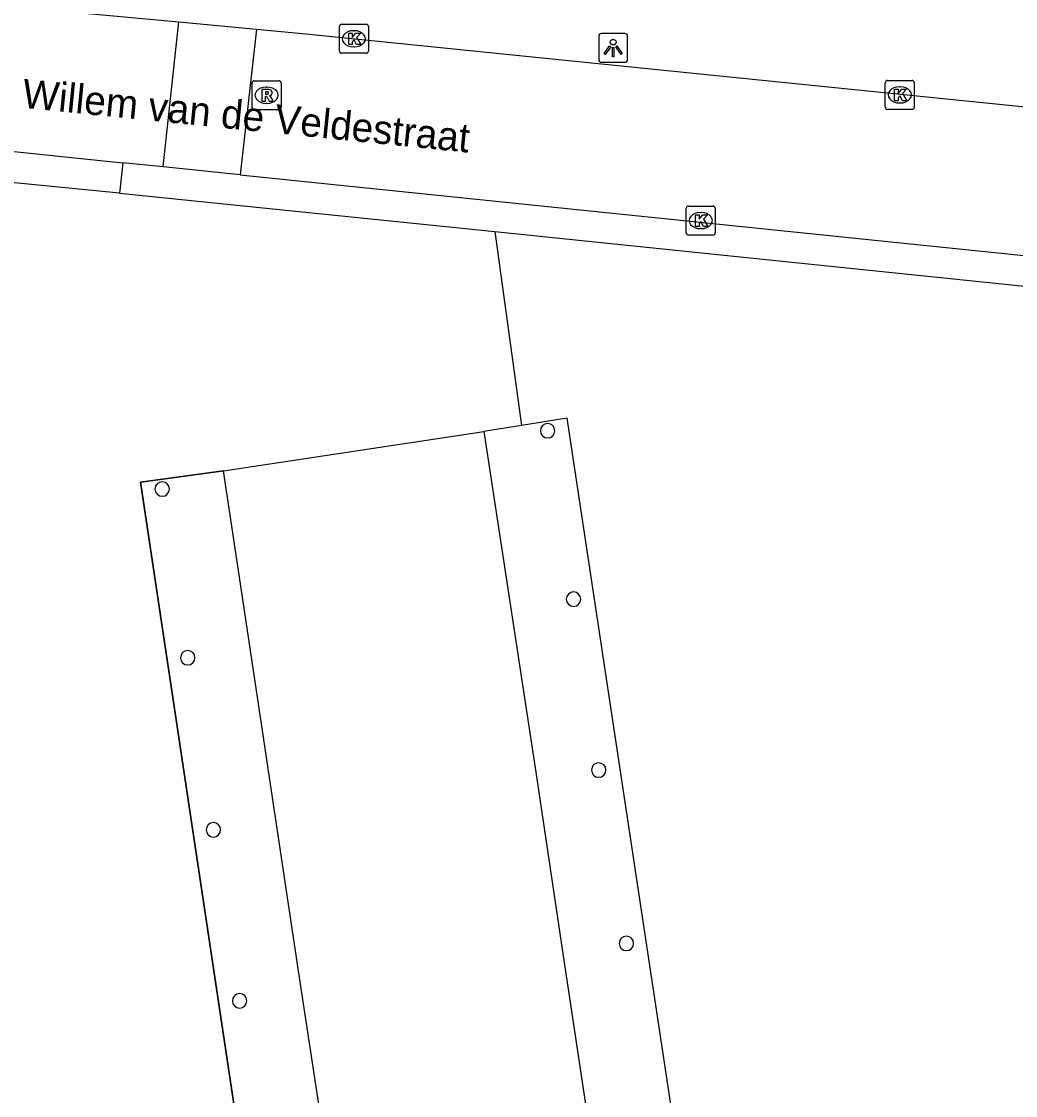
# Model space of a CAD drawing. Extents: x 163010 to 163853, y 382793 to 383982.
# Drawn here: x 163198.03 to 163232.4, y 383366.94 to 383404.07 of the extents above; entities that cross this region are included whole.
import ezdxf

# ---------------------------------------------------------------- set-up
doc = ezdxf.new("R2010")
doc.units = 0
for name, color, linetype in [('IMGEO_Kolk', 7, 'Continuous'), ('IMGEO_Lichtpunt', 7, 'Continuous'), ('IMGEO_Openbare_ruimte_label', 7, 'Continuous'), ('IMGEO_Pand', 7, 'Continuous'), ('IMGEO_Pand_overbouw', 7, 'Continuous'), ('IMGEO_Rijbaan_lokaal_open', 7, 'Continuous'), ('IMGEO_Rioolput', 7, 'Continuous'), ('IMGEO_Voetpad_open', 7, 'Continuous')]:
    doc.layers.add(name, color=color, linetype=linetype)

msp = doc.modelspace()

# ---------------------------------------------------------------- linework, layer by layer
at = {"layer": 'IMGEO_Kolk'}
for p, q in [((163209.021, 383403.045), (163209.021, 383403.897)), ((163209.096, 383403.971), (163209.948, 383403.971)), ((163210.022, 383403.897), (163210.022, 383403.045)), ((163209.509, 383403.751), (163209.534, 383403.751)), ((163209.532, 383403.191), (163209.507, 383403.191)), ((163209.948, 383402.971), (163209.096, 383402.971)), ((163227.976, 383402.032), (163228.828, 383402.032)), ((163227.901, 383401.106), (163227.901, 383401.958)), ((163228.389, 383401.812), (163228.414, 383401.812)), ((163228.902, 383401.958), (163228.902, 383401.106)), ((163228.828, 383401.032), (163227.976, 383401.032)), ((163228.412, 383401.252), (163228.387, 383401.252)), ((163221.017, 383396.762), (163221.017, 383397.614)), ((163221.092, 383397.688), (163221.944, 383397.688)), ((163222.018, 383397.614), (163222.018, 383396.762)), ((163221.505, 383397.468), (163221.53, 383397.468)), ((163221.528, 383396.908), (163221.503, 383396.908)), ((163221.944, 383396.688), (163221.092, 383396.688))]:
    msp.add_line(p, q, dxfattribs=at)
for points in [[(163209.021, 383403.045), (163209.021, 383403.897)], [(163209.096, 383403.971), (163209.948, 383403.971)], [(163210.022, 383403.897), (163210.022, 383403.045)], [(163209.342, 383403.671), (163209.465, 383403.671), (163209.465, 383403.52), (163209.595, 383403.671), (163209.759, 383403.671), (163209.613, 383403.52), (163209.766, 383403.271), (163209.614, 383403.271), (163209.529, 383403.435), (163209.465, 383403.368), (163209.465, 383403.271), (163209.342, 383403.271), (163209.342, 383403.671)], [(163209.948, 383402.971), (163209.096, 383402.971)], [(163227.976, 383402.032), (163228.828, 383402.032)], [(163227.901, 383401.106), (163227.901, 383401.958)], [(163228.222, 383401.732), (163228.345, 383401.732), (163228.345, 383401.581), (163228.475, 383401.732), (163228.639, 383401.732), (163228.493, 383401.581), (163228.646, 383401.332), (163228.494, 383401.332), (163228.409, 383401.496), (163228.345, 383401.429), (163228.345, 383401.332), (163228.222, 383401.332), (163228.222, 383401.732)], [(163228.902, 383401.958), (163228.902, 383401.106)], [(163228.828, 383401.032), (163227.976, 383401.032)], [(163221.017, 383396.762), (163221.017, 383397.614)], [(163221.092, 383397.688), (163221.944, 383397.688)], [(163222.018, 383397.614), (163222.018, 383396.762)], [(163221.338, 383397.388), (163221.461, 383397.388), (163221.461, 383397.237), (163221.591, 383397.388), (163221.755, 383397.388), (163221.609, 383397.237), (163221.762, 383396.988), (163221.61, 383396.988), (163221.525, 383397.152), (163221.461, 383397.085), (163221.461, 383396.988), (163221.338, 383396.988), (163221.338, 383397.388)], [(163221.944, 383396.688), (163221.092, 383396.688)]]:
    msp.add_lwpolyline(points, dxfattribs=at)
for centre, start, end in [((163209.098, 383403.895), 91.552, 178.448), ((163209.098, 383403.895), 91.552, 178.448), ((163209.946, 383403.895), 1.552, 88.448), ((163209.946, 383403.895), 1.552, 88.448), ((163209.098, 383403.047), 181.552, 268.448), ((163209.098, 383403.047), 181.552, 268.448), ((163209.946, 383403.047), 271.552, 358.448), ((163209.946, 383403.047), 271.552, 358.448), ((163227.978, 383401.956), 91.552, 178.448), ((163227.978, 383401.956), 91.552, 178.448), ((163228.826, 383401.956), 1.552, 88.448), ((163228.826, 383401.956), 1.552, 88.448), ((163227.978, 383401.108), 181.552, 268.448), ((163227.978, 383401.108), 181.552, 268.448), ((163228.826, 383401.108), 271.552, 358.448), ((163228.826, 383401.108), 271.552, 358.448), ((163221.094, 383397.612), 91.552, 178.448), ((163221.094, 383397.612), 91.552, 178.448), ((163221.942, 383397.612), 1.552, 88.448), ((163221.942, 383397.612), 1.552, 88.448), ((163221.094, 383396.764), 181.552, 268.448), ((163221.094, 383396.764), 181.552, 268.448), ((163221.942, 383396.764), 271.552, 358.448), ((163221.942, 383396.764), 271.552, 358.448)]:
    msp.add_arc(centre, 0.0765, start, end, dxfattribs=at)
for centre, major_axis, ratio, start_param, end_param in [((163209.508, 383403.471), (-0.387, 0.002), 0.722429, 4.712389, 7.853982), ((163209.533, 383403.471), (-0.39, 0.002), 0.717154, 1.570796, 4.712389), ((163228.388, 383401.532), (-0.387, 0.002), 0.722429, 4.712389, 7.853982), ((163228.413, 383401.532), (-0.39, 0.002), 0.717154, 1.570796, 4.712389), ((163221.504, 383397.188), (-0.387, 0.002), 0.722429, 4.712389, 7.853982), ((163221.529, 383397.188), (-0.39, 0.002), 0.717154, 1.570796, 4.712389)]:
    msp.add_ellipse(centre, major_axis=major_axis, ratio=ratio, start_param=start_param, end_param=end_param, dxfattribs=at)
at = {"layer": 'IMGEO_Lichtpunt'}
for p, q in [((163217.991, 383403.559), (163217.991, 383402.752)), ((163217.991, 383403.559), (163217.991, 383402.752)), ((163218.893, 383403.654), (163218.085, 383403.654)), ((163218.893, 383403.654), (163218.085, 383403.654)), ((163218.987, 383402.752), (163218.987, 383403.559)), ((163218.987, 383402.752), (163218.987, 383403.559)), ((163218.085, 383402.658), (163218.893, 383402.658)), ((163218.085, 383402.658), (163218.893, 383402.658))]:
    msp.add_line(p, q, dxfattribs=at)
for points in [[(163218.365, 383403.223), (163218.404, 383403.195), (163218.216, 383402.933), (163218.178, 383402.96), (163218.365, 383403.223)], [(163218.467, 383403.175), (163218.514, 383403.175), (163218.514, 383402.853), (163218.467, 383402.853), (163218.467, 383403.175)], [(163218.577, 383403.195), (163218.615, 383403.222), (163218.802, 383402.96), (163218.763, 383402.932), (163218.577, 383403.195)]]:
    msp.add_lwpolyline(points, dxfattribs=at)
msp.add_circle((163218.49, 383403.357), 0.0994, dxfattribs=at)
for centre, start, end in [((163218.085, 383403.559), 90, 180), ((163218.085, 383403.559), 90, 180), ((163218.893, 383403.559), 0, 90), ((163218.893, 383403.559), 0, 90), ((163218.085, 383402.752), 180, 270), ((163218.085, 383402.752), 180, 270), ((163218.893, 383402.752), 270, 0), ((163218.893, 383402.752), 270, 360)]:
    msp.add_arc(centre, 0.0946, start, end, dxfattribs=at)
at = {"layer": 'IMGEO_Pand'}
for points in [[(163205.008, 383388.541), (163214.019, 383389.896)], [(163214.019, 383389.896), (163215.811, 383378.119), (163216.729, 383372), (163217.672, 383365.721), (163218.489, 383360.307), (163219.424, 383354.102), (163221.206, 383342.268), (163222.117, 383336.203), (163223.07, 383329.86), (163223.887, 383324.464), (163224.823, 383318.307), (163225.771, 383312.064), (163226.572, 383306.656), (163227.544, 383300.293)], [(163218.49, 383298.916), (163217.531, 383305.316), (163216.715, 383310.736), (163215.782, 383316.947), (163214.042, 383328.531), (163213.089, 383334.846), (163212.171, 383340.926), (163211.368, 383346.337), (163210.397, 383352.744), (163209.451, 383358.986), (163208.652, 383364.371), (163207.704, 383370.643), (163206.776, 383376.781), (163205.973, 383382.176), (163205.008, 383388.541)]]:
    msp.add_lwpolyline(points, dxfattribs=at)
for centre, start, end in [((163216.223, 383389.924), 90, 270), ((163216.223, 383389.924), 270, 90), ((163202.893, 383387.908), 90, 270), ((163202.893, 383387.908), 270, 90), ((163217.119, 383384.099), 90, 270), ((163217.119, 383384.099), 270, 90), ((163203.777, 383382.075), 90, 270), ((163203.777, 383382.075), 270, 90), ((163217.988, 383378.193), 90, 270), ((163217.988, 383378.193), 270, 90), ((163204.662, 383376.126), 90, 270), ((163204.662, 383376.126), 270, 90), ((163218.947, 383372.202), 90, 270), ((163218.947, 383372.202), 270, 90), ((163205.571, 383370.214), 90, 270), ((163205.571, 383370.214), 270, 90)]:
    msp.add_arc(centre, 0.25, start, end, dxfattribs=at)
at = {"layer": 'IMGEO_Pand_overbouw'}
for points in [[(163216.895, 383390.359), (163215.316, 383390.105), (163214.019, 383389.896), (163215.811, 383378.119), (163216.729, 383372), (163217.672, 383365.721), (163218.489, 383360.307), (163219.424, 383354.102), (163221.206, 383342.268), (163222.117, 383336.203), (163223.07, 383329.86), (163223.887, 383324.464), (163224.823, 383318.307), (163225.771, 383312.064), (163226.572, 383306.656), (163227.544, 383300.293), (163230.444, 383300.724)], [(163206.776, 383376.781), (163205.973, 383382.176), (163205.008, 383388.541), (163202.14, 383388.145), (163215.602, 383298.476), (163218.49, 383298.916), (163217.531, 383305.316), (163216.715, 383310.736), (163215.782, 383316.947), (163214.042, 383328.531), (163213.089, 383334.846), (163212.171, 383340.926), (163211.368, 383346.337), (163210.397, 383352.744), (163209.451, 383358.986), (163208.652, 383364.371), (163207.704, 383370.643)]]:
    msp.add_lwpolyline(points, close=True, dxfattribs=at)
at = {"layer": 'IMGEO_Rijbaan_lokaal_open'}
for points in [[(163190.727, 383405.303), (163191.182, 383405.246), (163192.544, 383405.077), (163203.464, 383404.058)], [(163202.925, 383399.045), (163203.464, 383404.058)], [(163203.464, 383404.058), (163206.155, 383403.807)], [(163206.155, 383403.807), (163205.589, 383398.77)], [(163206.155, 383403.807), (163207.861, 383403.648), (163244.897, 383399.882)], [(163194.875, 383399.875), (163201.537, 383399.188)], [(163202.925, 383399.045), (163201.537, 383399.188)], [(163201.42, 383398.14), (163195.429, 383398.72)], [(163205.589, 383398.77), (163202.925, 383399.045)], [(163205.589, 383398.77), (163238.626, 383395.365)], [(163201.42, 383398.14), (163214.391, 383396.806)], [(163214.391, 383396.806), (163215.316, 383390.105)], [(163215.316, 383390.105), (163214.019, 383389.896)], [(163215.602, 383298.476), (163202.14, 383388.145), (163205.008, 383388.541)]]:
    msp.add_lwpolyline(points, dxfattribs=at)
at = {"layer": 'IMGEO_Rioolput'}
for p, q in [((163206.002, 383401.092), (163206.002, 383401.944)), ((163206.077, 383402.018), (163206.929, 383402.018)), ((163206.49, 383401.798), (163206.515, 383401.798)), ((163207.003, 383401.944), (163207.003, 383401.092)), ((163206.929, 383401.018), (163206.077, 383401.018)), ((163206.513, 383401.238), (163206.488, 383401.238))]:
    msp.add_line(p, q, dxfattribs=at)
for points in [[(163206.002, 383401.092), (163206.002, 383401.944)], [(163206.077, 383402.018), (163206.929, 383402.018)], [(163206.591, 383401.716), (163206.339, 383401.718), (163206.339, 383401.318)], [(163207.003, 383401.944), (163207.003, 383401.092)], [(163206.339, 383401.318), (163206.463, 383401.318), (163206.463, 383401.48), (163206.474, 383401.48)], [(163206.517, 383401.637), (163206.463, 383401.637), (163206.463, 383401.556)], [(163206.463, 383401.556), (163206.515, 383401.556)], [(163206.521, 383401.451), (163206.592, 383401.318), (163206.732, 383401.318), (163206.667, 383401.444)], [(163206.929, 383401.018), (163206.077, 383401.018)]]:
    msp.add_lwpolyline(points, dxfattribs=at)
for centre, radius, start, end in [((163206.079, 383401.942), 0.0765, 91.552, 178.448), ((163206.079, 383401.942), 0.0765, 91.552, 178.448), ((163206.59, 383401.606), 0.109, 350.3612, 89.416), ((163206.927, 383401.942), 0.0765, 1.552, 88.448), ((163206.927, 383401.942), 0.0765, 1.552, 88.448), ((163206.473, 383401.427), 0.0533, 26.0293, 88.6989), ((163206.499, 383401.745), 0.19, 274.7715, 282.9687), ((163206.523, 383401.541), 0.0964, 77.0061, 93.1865), ((163206.537, 383401.598), 0.0378, 276.6634, 79.6772), ((163206.588, 383401.606), 0.112, 277.5842, 350.9817), ((163206.572, 383401.391), 0.108, 29.5134, 73.7905), ((163206.079, 383401.094), 0.0765, 181.552, 268.448), ((163206.079, 383401.094), 0.0765, 181.552, 268.448), ((163206.927, 383401.094), 0.0765, 271.552, 358.448), ((163206.927, 383401.094), 0.0765, 271.552, 358.448)]:
    msp.add_arc(centre, radius, start, end, dxfattribs=at)
for centre, major_axis, ratio, start_param, end_param in [((163206.489, 383401.518), (-0.387, 0.002), 0.722429, 4.712389, 7.853982), ((163206.514, 383401.518), (-0.39, 0.002), 0.717154, 1.570796, 4.712389)]:
    msp.add_ellipse(centre, major_axis=major_axis, ratio=ratio, start_param=start_param, end_param=end_param, dxfattribs=at)
at = {"layer": 'IMGEO_Voetpad_open'}
for points in [[(163201.537, 383399.188), (163201.42, 383398.14)], [(163214.391, 383396.806), (163235.287, 383394.655), (163238.513, 383394.323)], [(163228.85, 383300.487), (163230.444, 383300.724), (163216.895, 383390.359), (163215.316, 383390.105)]]:
    msp.add_lwpolyline(points, dxfattribs=at)

# ---------------------------------------------------------------- texts
at = {"layer": 'IMGEO_Openbare_ruimte_label'}
msp.add_text('Willem van de Veldestraat', height=1, rotation=354.2609, dxfattribs=at).set_placement((163198.019, 383401.092))
msp.add_text('Willem van de Veldestraat', height=1, rotation=354.2609, dxfattribs=at).set_placement((163198.019, 383401.092))

doc.saveas('drawing.dxf')
